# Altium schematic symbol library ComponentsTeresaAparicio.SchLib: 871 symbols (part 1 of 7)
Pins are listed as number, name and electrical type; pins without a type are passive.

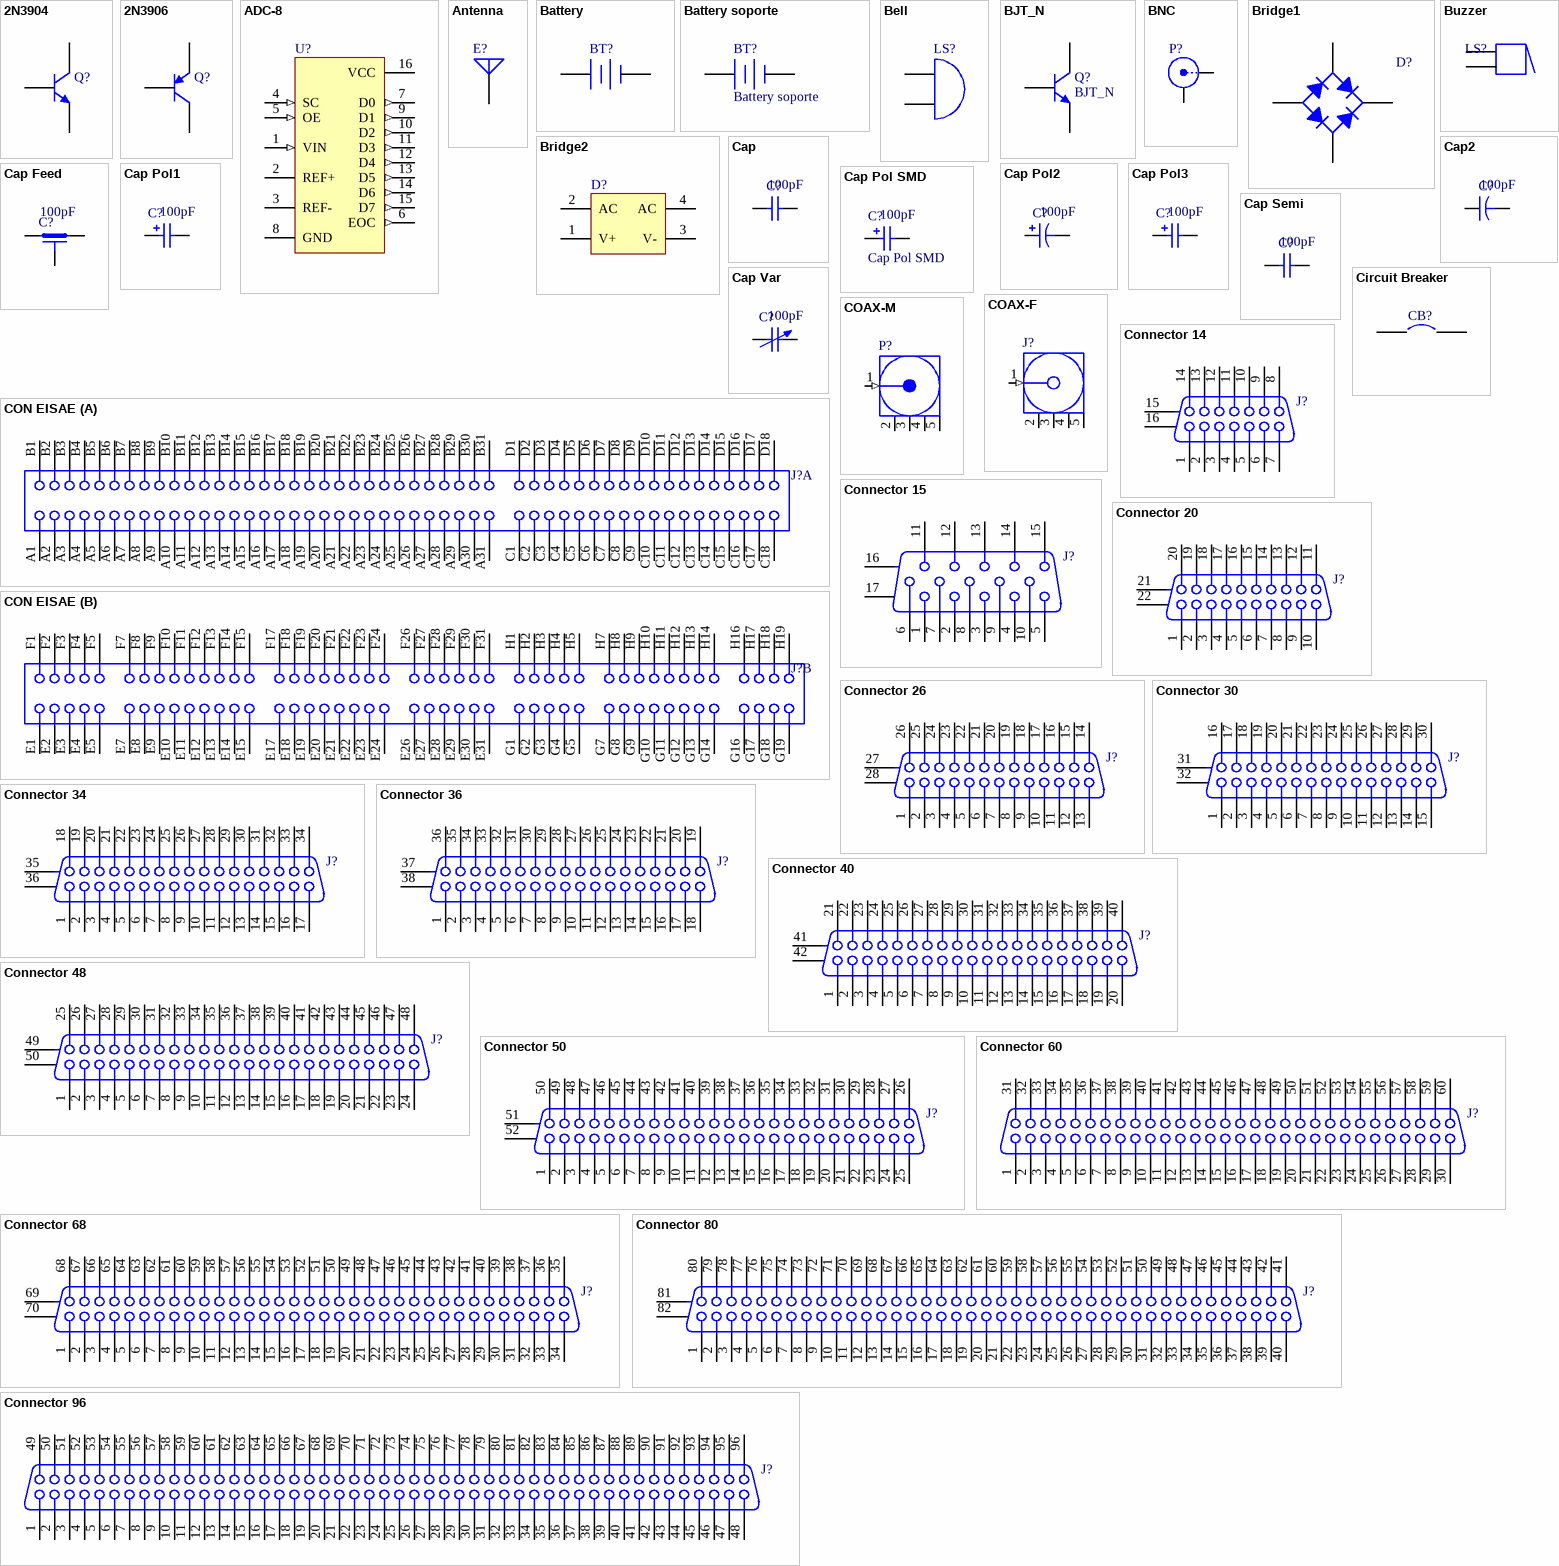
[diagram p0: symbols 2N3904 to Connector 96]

## 2N3904
designator Q?
NPN General Purpose Amplifier
footprint TO-92A (TO, Flat Index; 3 In-Line, Axial Leads; Body Dia. 4.5mm; Leads 0.51 x 0.48 mm (max))
simulation model 2N3904 (NPN)
signal-integrity model 2N3904
pins: 1 E, 2 B, 3 C

## 2N3906
designator Q?
PNP General Purpose Amplifier
footprint TO-92A (TO, Flat Index; 3 In-Line, Axial Leads; Body Dia. 4.5mm; Leads 0.51 x 0.48 mm (max))
simulation model 2N3906 (PNP)
signal-integrity model 2N3906
pins: 1 E, 2 B, 3 C

## ADC-8
designator U?
Generic 8-Bit A/D Converter
footprint SOT403-1_N (TSOP, 16-Leads, Body 5x4.4mm, Pitch 0.65mm, IPC Medium Density)
footprint SOT403-1_L (TSOP, 16-Leads, Body 5x4.4mm, Pitch 0.65mm, IPC High Density)
footprint SOT403-1_M (TSOP, 16-Leads, Body 5x4.4mm, Pitch 0.65mm, IPC Low Density)
simulation model ADC8 (SIMCODE)
pins: 1 VIN (in), 2 REF+, 3 REF-, 4 SC (in), 5 OE (in), 6 EOC (out), 7 D0 (out), 8 GND (power), 9 D1 (out), 10 D2 (out), 11 D3 (out), 12 D4 (out), 13 D5 (out), 14 D6 (out), 15 D7 (out), 16 VCC (power)

## Antenna
designator E?
Generic Antenna
footprint PIN1 (Generic Antenna; 1 Lead)
pins: 1 A

## Battery
designator BT?
Multicell Battery
footprint BAT_Holder (Battery; 2 Leads)
pins: 1 +, 2 -

## Battery soporte
designator BT?
Multicell Battery
footprint BAT-2 (Battery; 2 Leads)
pins: 1 +, 2 -

## Bell
designator LS?
Electrical Bell
footprint PIN2 (Electrical Bell; 2 Leads)
pins: 1 A, 2 B

## BJT_N
designator Q?
NPN General Purpose Amplifier
footprint TO-92A (TO, Flat Index; 3 In-Line, Axial Leads; Body Dia. 4.5mm; Leads 0.51 x 0.48 mm (max))
simulation model 2N3904 (NPN)
signal-integrity model 2N3904
pins: 1 E, 2 B, 3 C

## BNC
designator P?
BNC Elbow Connector
footprint BNC_RA CON (Connector; BNC Elbow)
signal-integrity model Connector
pins: 1 X, 2 Y

## Bridge1
designator D?
Full Wave Diode Bridge
footprint D-38 (Bridge Rectifier; 4 Terminals; Body 9.4 x 9.4 mm (typ); Pitch 5.08 mm)
simulation model BRIDGE (Spice Subcircuit)
pins: 1 K, 2 C, 3 A, 4 C

## Bridge2
designator D?
Diode Bridge
footprint D-46_6A (Bridge Rectifier; 4 Terminals; Body 16.8 x 16.8 mm (typ); Pitch 10.67 mm)
simulation model BRIDGE (Spice Subcircuit)
pins: 1 V+, 2 AC, 3 V-, 4 AC

## Buzzer
designator LS?
Magnetic Transducer Buzzer
footprint Buzzer 5v
pins: 1, 2
1 alternate drawing of the same symbol

## Cap
designator C?  value 100pF
Capacitor
footprint RAD-0.3 (Radial Cap, Thru-Hole; 2 Leads; 0.3 in Pin Spacing)
simulation model CAP (Capacitor)
signal-integrity model Cap
pins: 1, 2

## Cap2
designator C?  value 100pF
Capacitor
footprint CAPR5-4X5 (Capacitor; 2 Leads)
simulation model CAP (Capacitor)
signal-integrity model Cap
pins: 1, 2

## Cap Feed
designator C?  value 100pF
Feed-Through Capacitor; Note: Commonly used for bypassing high-frequency currents to chassis
footprint VR4 (Thru-Hole; 3 Leads)
signal-integrity model Cap Feed
pins: 1, 2, 3

## Cap Pol1
designator C?  value 100pF
Polarized Capacitor (Radial)
footprint RB7.6-15 (Polarized Capacitor (Radial); 2 Leads)
simulation model CAP (Capacitor)
signal-integrity model Cap Pol
pins: 1, 2
1 alternate drawing of the same symbol

## Cap Pol2
designator C?  value 100pF
Polarized Capacitor (Axial)
footprint POLAR0.8 (Polarized Capacitor; 2 Leads)
simulation model CAP (Capacitor)
signal-integrity model Cap Pol
pins: 1, 2
1 alternate drawing of the same symbol

## Cap Pol3
designator C?  value 100pF
Polarized Capacitor (Surface Mount)
footprint C0805 (Chip Capacitor, Body 2.0x1.3mm, IPC High Density)
footprint 1812 (Chip Capacitor, Body 4.5x3.2mm, IPC High Density)
footprint 1825 (Chip Capacitor, Body 4.5x6.4mm, IPC High Density)
footprint C2225 (Chip Capacitor, Body 5.7x6.4mm, IPC High Density)
footprint 2220 (Chip Capacitor, Body 5.7x5.0mm, IPC High Density)
simulation model CAP (Capacitor)
signal-integrity model Cap Pol
pins: 1, 2
1 alternate drawing of the same symbol

## Cap Pol SMD
designator C?  value 100pF
Polarized Capacitor (Radial)
footprint C0805 (Chip Capacitor, Body 2.0x1.3mm, IPC High Density)
simulation model CAP (Capacitor)
signal-integrity model Cap Pol
pins: 1, 2
1 alternate drawing of the same symbol

## Cap Semi
designator C?  value 100pF
Capacitor (Semiconductor SIM Model)
footprint C1206 (Chip Capacitor, Body 3.2x1.6mm, IPC High Density)
footprint 0402 (Chip Capacitor, Body 1.0x0.5mm, IPC High Density)
footprint C2512 (Chip Capacitor, Body 2.54x1.27mm, IPC High Density)
footprint 1608[0603] (Chip Capacitor, Body 1.6x0.8mm, IPC High Density)
footprint C1210 (Chip Capacitor, Body 3.2x2.5mm, IPC High Density)
simulation model CAP (Semiconductor Capacitor)
signal-integrity model C0805
footprint C0805 (Chip Capacitor, Body 2.0x1.3mm, IPC High Density)
pins: 1, 2

## Cap Var
designator C?  value 100pF
Variable or Adjustable Capacitor
footprint C1210_N (Chip Capacitor, Body 3.2x2.5mm, IPC Medium Density)
footprint C1210_L (Chip Capacitor, Body 3.2x2.5mm, IPC High Density)
footprint C1210_M (Chip Capacitor, Body 3.2x2.5mm, IPC Low Density)
signal-integrity model Cap Var
pins: 1, 2

## Circuit Breaker
designator CB?
Circuit Breaker
footprint SPST-2 (Switch; 2 Leads)
pins: 1, 2

## COAX-F
designator J?
RF Coaxial PCB Connector, MCX; Thru-Hole, Right-Angle Mount Socket, Blunt Post Terminal, 50 Ohm Impedance; PCB_Layout: Complies with manufacturer's recommendation.; DrillSize: Corresponds to nominal value.
footprint MCX5.08-H5 (Connector; RF Coaxial, MCX, Thru-Hole; 5 Position; Right-Angle)
pins: 1 Signal (in) "Signal Pin", 2 GND (power), 3 GND (power), 4 GND (power), 5 GND (power)

## COAX-M
designator P?
RF Coaxial PCB Connector, MMCX; Thru-Hole, Vertical Mount Plug,  50 Ohm Impedance; PackageDocument: Rev. A, 16-Jun-1997; PCB_Layout: Complies with manufacturer's recommendation.; DrillSize: Corresponds to nominal value.
footprint MMCX2.54-V5 (Connector; RF Coaxial, MMCX, Thru-Hole; 5 Position; Vertical)
pins: 1 Signal (in) "Signal Pin", 2 GND (power), 3 GND (power), 4 GND (power), 5 GND (power)

## CON EISAE
designator J?
EISA Connector, 188 Positions, Vertical, Pitch 1.27mm; ContactPlating: Gold Flash; PCB_Layout: Complies with manufacturer's recommendation.; DrillSize: Corresponds to nominal value.; Note: Access Keys, E6 E16 E25 F6 F16 F25 G6 G15 H6 H15 not shown.
footprint CARD1.27-2V188 (Connector; EISA, Thru-Hole; 188 Position; Vertical; Pitch 1.27 mm)
signal-integrity model EISA
part A pins: A1 CHCHK#, A2 SD7, A3 SD6, A4 SD5, A5 SD4, A6 SD3, A7 SD2, A8 SD1, A9 SD0, A10 CHRDY, A11 AEN, A12 SA19, A13 SA18, A14 SA17, A15 SA16, A16 SA15, A17 SA14, A18 SA13, A19 SA12, A20 SA11, A21 SA10, A22 SA9, A23 SA8, A24 SA7, A25 SA6, A26 SA5, A27 SA4, A28 SA3, A29 SA2, A30 SA1, A31 SA0, B1 GND "Ground", B2 RESDRV#, B3 +5V "+5 VDC", B4 IRQ2, B5 -5V, B6 DRQ2, B7 -12V, B8 NOWS#, B9 +12V "+12 VDC", B10 GND, B11 SMWTC#, B12 SMRDC#, B13 IOWC#, B14 IORC#, B15 DAK3#, B16 DRQ3, B17 DAK1#, B18 DRQ1, B19 REFRESH#, B20 BCLK, B21 IRQ7, B22 IRQ6, B23 IRQ5, B24 IRQ4, B25 IRQ3, B26 DAK2#, B27 TC, B28 BALE, B29 +5V "+5 VDC", B30 OSC, B31 GND "Ground", C1 SBHE#, C2 LA23, C3 LA22, C4 LA21, C5 LA20, C6 LA19, C7 LA18, C8 LA17, C9 MRDC#, C10 MWTC#, C11 SD8, C12 SD9, C13 SD10, C14 SD11, C15 SD12, C16 SD13, C17 SD14, C18 SD15, D1 M16#, D2 IO16#, D3 IRQ10, D4 IRQ11, D5 IRQ12, D6 IRQ13, D7 IRQ14, D8 DAK0#, D9 DRQ0, D10 DAK5#, D11 DRQ5, D12 DAK6#, D13 DRQ65, D14 DAK7#, D15 DRQ7, D16 +5V "+5 VDC", D17 MASTER16#, D18 GND "Ground"
part B pins: E1 CMD# "Command Phase", E2 START# "Start Phase", E3 EXRDY "EISA Ready", E4 EX32# "EISA Slave Size 32", E5 GND "Ground", E7 EX16# "EISA Slave Size 16", E8 SLBURST# "Slave Burst", E9 MSBURST# "Master Burst", E10 W/R# "Write/Read", E11 GND "Ground", E12 RES "Reserved", E13 RES "Reserved", E14 RES "Reserved", E15 GND "Ground", E17 BE1# "Byte Enable 1", E18 LA31# "Latchable Addressline 31", E19 GND "Ground", E20 LA30# "Latchable Addressline 30", E21 LA28# "Latchable Addressline 28", E22 LA27# "Latchable Addressline 27", E23 LA25# "Latchable Addressline 25", E24 GND "Ground", E26 LA15 "Latchable Addressline 15", E27 LA13 "Latchable Addressline 13", E28 LA12 "Latchable Addressline 12", E29 LA11 "Latchable Addressline 11", E30 GND "Ground", E31 LA9 "Latchable Addressline 9", F1 GND "Ground", F2 +5V "+5 VDC", F3 +5V "+5 VDC", F4 RES "Reserved", F5 RES "Reserved", F7 RES "Reserved", F8 RES "Reserved", F9 +12V "+12 VDC", F10 M/IO# "Memory/Input-Output", F11 LOCK# "Lock bus", F12 RES "Reserved", F13 GND "Ground", F14 RES "Reserved", F15 BE3# "Byte Enable 3", F17 BE2# "Byte Enable 2", F18 BE0# "Byte Enable 0", F19 GND "Ground", F20 +5V "+5 VDC", F21 LA29# "Latchable Addressline 29", F22 GND "Ground", F23 LA26# "Latchable Addressline 26", F24 LA24# "Latchable Addressline 24", F26 LA16 "Latchable Addressline 16", F27 LA14 "Latchable Addressline 14", F28 +5V "+5 VDC", F29 +5V "+5 VDC", F30 GND "Ground", F31 LA10 "Latchable Addressline 10", G1 LA7 "Latchable Addressline 7", G2 GND "Ground", G3 LA4 "Latchable Addressline 4", G4 LA3 "Latchable Addressline 3", G5 GND "Ground", G7 D17 "Data 17", G8 D19 "Data 19", G9 D20 "Data 20", G10 D22 "Data 22", G11 GND "Ground", G12 D25 "Data 25", G13 D26 "Data 26", G14 D28 "Data 28", G16 GND "Ground", G17 D30 "Data 30", G18 D31 "Data 31", G19 MREQx "Master Request", H1 LA8 "Latchable Addressline 8", H2 LA6 "Latchable Addressline 6", H3 LA5 "Latchable Addressline 5", H4 +5V "+5 VDC", H5 LA2 "Latchable Addressline 2", H7 D16 "Data 16", H8 D18 "Data 18", H9 GND "Ground", H10 D21 "Data 21", H11 D23 "Data 23", H12 D24 "Data 24", H13 GND "Ground", H14 D27 "Data 27", H16 D29 "Data 29", H17 +5V "+5 VDC", H18 +5V "+5 VDC", H19 MAKx "Master Acknowledge"

## Connector 14
designator J?
Receptacle Header Assemby; PackageDocument: B; Positions: 14
footprint CHAMP1.27-2H14A (Connector; 14 Position; Right Angle; Pitch 1.27 mm)
signal-integrity model Connector
pins: 1, 2, 3, 4, 5, 6, 7, 8, 9, 10, 11, 12, 13, 14, 15 MH1, 16 MH2

## Connector 15
designator J?
Receptacle Assembly, 15-Pin, Sim Line Connector; PackageDocument: B; Positions: 15; Gender: Receptacle Header
footprint 050DSUB0.762-4H15 (Connector; D Subminiature; 15 Position; Right Angle; Pitch 0.762 mm)
signal-integrity model Connector
pins: 1, 2, 3, 4, 5, 6, 7, 8, 9, 10, 11, 12, 13, 14, 15, 16 MH1, 17 MH2

## Connector 20
designator J?
Receptacle Header Assemby; PackageDocument: B; Positions: 20
footprint CHAMP1.27-2H20 (Connector; 20 Position; Right Angle; Pitch 1.27 mm)
signal-integrity model Connector
pins: 1, 2, 3, 4, 5, 6, 7, 8, 9, 10, 11, 12, 13, 14, 15, 16, 17, 18, 19, 20, 21 MH1, 22 MH2

## Connector 26
designator J?
Receptacle Header Assemby; PackageDocument: B; Positions: 26
footprint CHAMP1.27-2H26 (Connector; 26 Position; Right Angle; Pitch 1.27 mm)
signal-integrity model Connector
pins: 1, 2, 3, 4, 5, 6, 7, 8, 9, 10, 11, 12, 13, 14, 15, 16, 17, 18, 19, 20, 21, 22, 23, 24, 25, 26, 27 MH1, 28 MH2

## Connector 30
designator J?
Plug Assembly, 30-Pin Connector; PackageDocument: E; Positions: 30; Gender: Receptacle Header
footprint 050DSUB1.27-2H30 (Connector; D Subminiature; 30 Position; Right Angle; Pitch 1.27 mm)
signal-integrity model Connector
pins: 1, 2, 3, 4, 5, 6, 7, 8, 9, 10, 11, 12, 13, 14, 15, 16, 17, 18, 19, 20, 21, 22, 23, 24, 25, 26, 27, 28, 29, 30, 31 MH1, 32 MH2

## Connector 34
designator J?
Plug Assembly, 34-Pin Connector; PackageDocument: F; Positions: 34; Gender: Receptacle Header
footprint 050DSUB1.27-2H34 (Connector; D Subminiature; 34 Position; Right Angle; Pitch 1.27 mm)
signal-integrity model Connector
pins: 1, 2, 3, 4, 5, 6, 7, 8, 9, 10, 11, 12, 13, 14, 15, 16, 17, 18, 19, 20, 21, 22, 23, 24, 25, 26, 27, 28, 29, 30, 31, 32, 33, 34, 35 MH1, 36 MH2

## Connector 36
designator J?
Receptacle Header Assemby; PackageDocument: B; Positions: 36
footprint CHAMP1.27-2H36 (Connector; 36 Position; Right Angle; Pitch 1.27 mm)
signal-integrity model Connector
pins: 1, 2, 3, 4, 5, 6, 7, 8, 9, 10, 11, 12, 13, 14, 15, 16, 17, 18, 19, 20, 21, 22, 23, 24, 25, 26, 27, 28, 29, 30, 31, 32, 33, 34, 35, 36, 37 MH1, 38 MH2

## Connector 40
designator J?
Plug Assembly, 40-Pin Connector; PackageDocument: E; Positions: 40; Gender: Receptacle Header
footprint 050DSUB1.27-2H40 (Connector; D Subminiature; 40 Position; Right Angle; Pitch 1.27 mm)
signal-integrity model Connector
pins: 1, 2, 3, 4, 5, 6, 7, 8, 9, 10, 11, 12, 13, 14, 15, 16, 17, 18, 19, 20, 21, 22, 23, 24, 25, 26, 27, 28, 29, 30, 31, 32, 33, 34, 35, 36, 37, 38, 39, 40, 41 MH1, 42 MH2

## Connector 48
designator J?
Plug Assembly, 48-Pin Connector; PackageDocument: F; Positions: 48; Gender: Receptacle Header
footprint 050DSUB1.27-2H48 (Connector; D Subminiature; 48 Position; Right Angle; Pitch 1.27 mm)
signal-integrity model Connector
pins: 1, 2, 3, 4, 5, 6, 7, 8, 9, 10, 11, 12, 13, 14, 15, 16, 17, 18, 19, 20, 21, 22, 23, 24, 25, 26, 27, 28, 29, 30, 31, 32, 33, 34, 35, 36, 37, 38, 39, 40, 41, 42, 43, 44, 45, 46, 47, 48, 49 MH1, 50 MH2

## Connector 50
designator J?
Receptacle Header Assemby; PackageDocument: B; Positions: 50
footprint CHAMP1.27-2H50 (Connector; 50 Position; Right Angle; Pitch 1.27 mm)
signal-integrity model Connector
pins: 1, 2, 3, 4, 5, 6, 7, 8, 9, 10, 11, 12, 13, 14, 15, 16, 17, 18, 19, 20, 21, 22, 23, 24, 25, 26, 27, 28, 29, 30, 31, 32, 33, 34, 35, 36, 37, 38, 39, 40, 41, 42, 43, 44, 45, 46, 47, 48, 49, 50, 51 MH1, 52 MH2

## Connector 60
designator J?
Plug Assembly, 60-Pin Connector; PackageDocument: D; Positions: 60; Gender: Receptacle Header
footprint 050DSUB1.27-V60 (Connector; D Subminiature; 60 Position; Vertical; Pitch 1.27 mm)
signal-integrity model Connector
pins: 1, 2, 3, 4, 5, 6, 7, 8, 9, 10, 11, 12, 13, 14, 15, 16, 17, 18, 19, 20, 21, 22, 23, 24, 25, 26, 27, 28, 29, 30, 31, 32, 33, 34, 35, 36, 37, 38, 39, 40, 41, 42, 43, 44, 45, 46, 47, 48, 49, 50, 51, 52, 53, 54, 55, 56, 57, 58, 59, 60

## Connector 68
designator J?
Receptacle Header Assemby; PackageDocument: B; Positions: 68
footprint CHAMP1.27-2H68 (Connector; 68 Position; Right Angle; Pitch 1.27 mm)
signal-integrity model Connector
pins: 1, 2, 3, 4, 5, 6, 7, 8, 9, 10, 11, 12, 13, 14, 15, 16, 17, 18, 19, 20, 21, 22, 23, 24, 25, 26, 27, 28, 29, 30, 31, 32, 33, 34, 35, 36, 37, 38, 39, 40, 41, 42, 43, 44, 45, 46, 47, 48, 49, 50, 51, 52, 53, 54, 55, 56, 57, 58, 59, 60, 61, 62, 63, 64, 65, 66, 67, 68, 69 MH1, 70 MH2

## Connector 80
designator J?
Receptacle Header Assemby; PackageDocument: C; Positions: 80
footprint CHAMP1.27-2V80 (Connector; 80 Position; Vertical; Pitch 1.27 mm)
signal-integrity model Connector
pins: 1, 2, 3, 4, 5, 6, 7, 8, 9, 10, 11, 12, 13, 14, 15, 16, 17, 18, 19, 20, 21, 22, 23, 24, 25, 26, 27, 28, 29, 30, 31, 32, 33, 34, 35, 36, 37, 38, 39, 40, 41, 42, 43, 44, 45, 46, 47, 48, 49, 50, 51, 52, 53, 54, 55, 56, 57, 58, 59, 60, 61, 62, 63, 64, 65, 66, 67, 68, 69, 70, 71, 72, 73, 74, 75, 76, 77, 78, 79, 80, 81 MH1, 82 MH2

## Connector 96
designator J?
Plug Assembly, 96-Pin Connector; PackageDocument: C; Positions: 96; Gender: Receptacle Header
footprint 050DSUB1.27-H96 (Connector; D Subminiature; 96 Position; Right Angle; Pitch 1.27 mm)
signal-integrity model Connector
pins: 1, 2, 3, 4, 5, 6, 7, 8, 9, 10, 11, 12, 13, 14, 15, 16, 17, 18, 19, 20, 21, 22, 23, 24, 25, 26, 27, 28, 29, 30, 31, 32, 33, 34, 35, 36, 37, 38, 39, 40, 41, 42, 43, 44, 45, 46, 47, 48, 49, 50, 51, 52, 53, 54, 55, 56, 57, 58, 59, 60, 61, 62, 63, 64, 65, 66, 67, 68, 69, 70, 71, 72, 73, 74, 75, 76, 77, 78, 79, 80, 81, 82, 83, 84, 85, 86, 87, 88, 89, 90, 91, 92, 93, 94, 95, 96

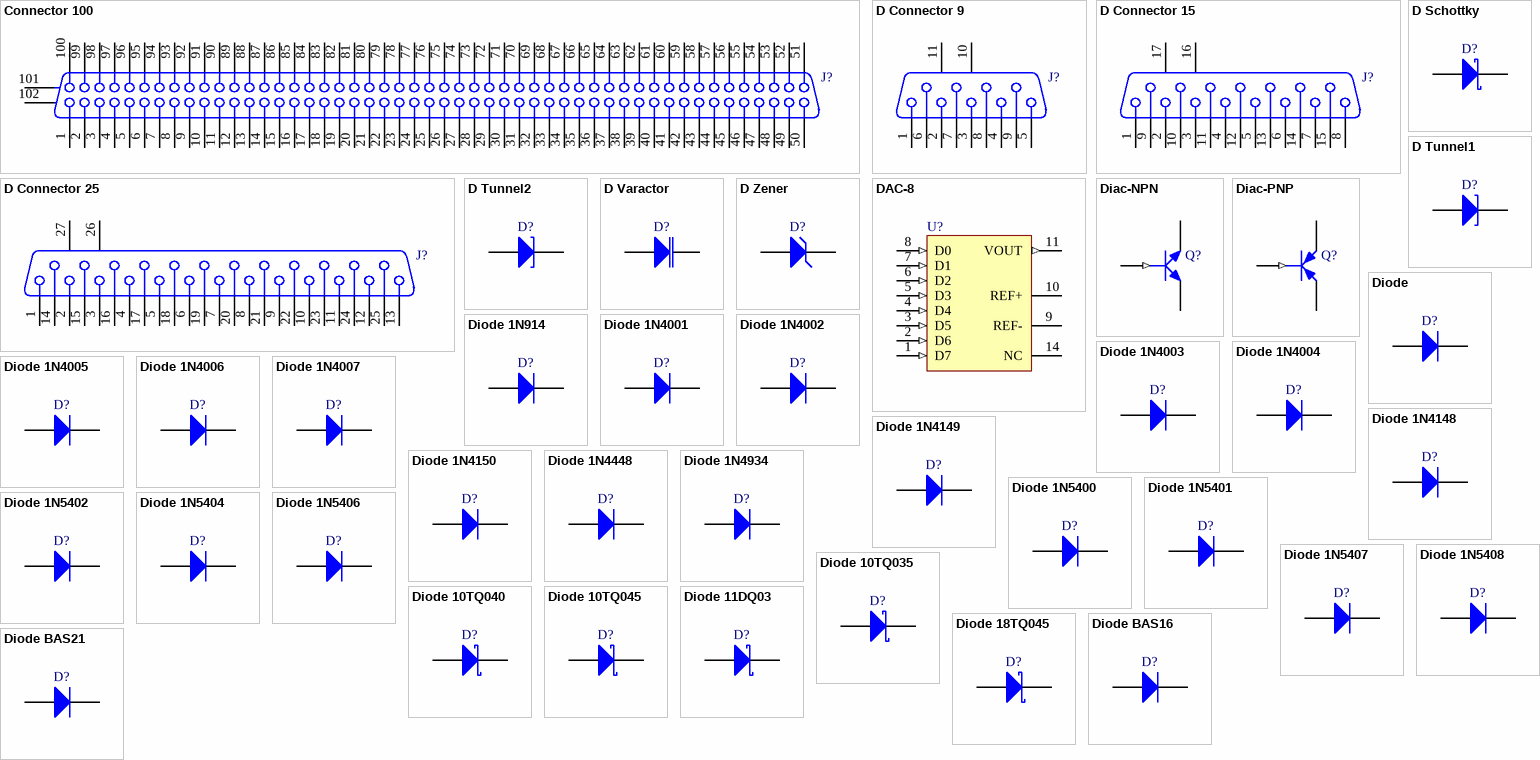
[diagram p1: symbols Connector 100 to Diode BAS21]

## Connector 100
designator J?
Receptacle Header Assemby; PackageDocument: B; Positions: 100
footprint CHAMP1.27-2H100 (Connector; 100 Position; Right Angle; Pitch 1.27 mm)
signal-integrity model Connector
pins: 1, 2, 3, 4, 5, 6, 7, 8, 9, 10, 11, 12, 13, 14, 15, 16, 17, 18, 19, 20, 21, 22, 23, 24, 25, 26, 27, 28, 29, 30, 31, 32, 33, 34, 35, 36, 37, 38, 39, 40, 41, 42, 43, 44, 45, 46, 47, 48, 49, 50, 51, 52, 53, 54, 55, 56, 57, 58, 59, 60, 61, 62, 63, 64, 65, 66, 67, 68, 69, 70, 71, 72, 73, 74, 75, 76, 77, 78, 79, 80, 81, 82, 83, 84, 85, 86, 87, 88, 89, 90, 91, 92, 93, 94, 95, 96, 97, 98, 99, 100, 101 MH1, 102 MH2

## D Connector 9
designator J?
Receptacle Assembly, 9 Position, Right Angle; PackageDocument: O; Positions: 9
footprint DSUB1.385-2H9 (Connector; D Subminiature; 9 Position; Right Angle; Pitch 1.385 mm)
signal-integrity model Connector
pins: 1, 2, 3, 4, 5, 6, 7, 8, 9, 10 MH1, 11 MH2

## D Connector 15
designator J?
Receptacle Assembly, 15 Position, Right Angle; PackageDocument: O; Positions: 15
footprint DSUB1.385-2H15 (Connector; D Subminiature; 15 Position; Right Angle; Pitch 1.385 mm)
signal-integrity model Connector
pins: 1, 2, 3, 4, 5, 6, 7, 8, 9, 10, 11, 12, 13, 14, 15, 16 MH1, 17 MH2

## D Connector 25
designator J?
Receptacle Assembly, 25 Position, Right Angle; PackageDocument: U; Positions: 25
footprint DSUB1.385-2H25A (Connector; D Subminiature; 25 Position; Right Angle; Pitch 1.385 mm)
signal-integrity model Connector
pins: 1, 2, 3, 4, 5, 6, 7, 8, 9, 10, 11, 12, 13, 14, 15, 16, 17, 18, 19, 20, 21, 22, 23, 24, 25, 26 MH1, 27 MH2

## D Schottky
designator D?
Schottky Diode
footprint SMB (DO-214-AA/SMB; 2 C-Bend Leads; Body 5.3 x 3.6 mm, inc. leads (LxW))
simulation model SKYDIODE (Diode)
signal-integrity model D Schottky
pins: 1 A, 2 K

## D Tunnel1
designator D?
Tunnel Diode - RLC Model
footprint 3.2X1.6X1.1 (SMT LED; 2 Flat Leads)
simulation model DTUNNEL1 (Spice Subcircuit)
signal-integrity model D Tunnel
pins: 1 A, 2 K

## D Tunnel2
designator D?
Tunnel Diode - Dependent Source Model
footprint DIODE-0.4 (Diode, Thru-Hole; 2 Leads; 0.4 in Pin Spacing)
simulation model DTUNNEL2 (Spice Subcircuit)
signal-integrity model D Tunnel
pins: 1 A, 2 K

## D Varactor
designator D?
Variable Capacitance Diode; Note: Pin 2 is not connected and not drawn.
footprint SOT23_N (SOT23, 3-Leads, Body 2.9x1.3mm, Pitch 0.95mm, Lead Span 2.3mm - Reverse Pinning, IPC Medium Density)
footprint SOT23_L (SOT23, 3-Leads, Body 2.9x1.3mm, Pitch 0.95mm, Lead Span 2.3mm - Reverse Pinning, IPC High Density)
footprint SOT23_M (SOT23, 3-Leads, Body 2.9x1.3mm, Pitch 0.95mm, Lead Span 2.3mm - Reverse Pinning, IPC Low Density)
simulation model BBY31 (Diode)
signal-integrity model D Varactor
pins: 1 K, 3 A

## D Zener
designator D?
Zener Diode
footprint DIODE-0.7 (Diode, Thru-Hole; 2 Leads; 0.7 in Pin Spacing)
simulation model ZENER (Diode)
signal-integrity model D Zener
pins: 1 A, 2 K

## DAC-8
designator U?
Generic 8-Bit D/A Converter
footprint SOT402-1_N (TSOP, 14-Leads, Body 5x4.4mm, Pitch 0.65mm, IPC Medium Density)
footprint SOT402-1_L (TSOP, 14-Leads, Body 5x4.4mm, Pitch 0.65mm, IPC High Density)
footprint SOT402-1_M (TSOP, 14-Leads, Body 5x4.4mm, Pitch 0.65mm, IPC Low Density)
simulation model DAC8 (SIMCODE)
pins: 1 D7 (in), 2 D6 (in), 3 D5 (in), 4 D4 (in), 5 D3 (in), 6 D2 (in), 7 D1 (in), 8 D0 (in), 9 REF-, 10 REF+, 11 VOUT (out), 12 GND (power) hidden to GND, 13 VCC (power) hidden to VCC, 14 NC

## Diac-NPN
designator Q?
DIAC
footprint TO-262-AA (TO, Thru-Hole, Vertical, Heatsink Mounted; 3 In-Line Leads; Pitch 2.54 mm)
pins: 1 B (in), 2 C, 3 E

## Diac-PNP
designator Q?
DIAC
footprint SOT89M (SOT89, 3-Leads, Body 4.5x2.4 mm, Pitch 1.5mm, Lead Span 4.1mm, IPC Low Density)
footprint SOT89N (SOT89, 3-Leads, Body 4.5x2.4 mm, Pitch 1.5mm, Lead Span 4.1mm, IPC Medium Density)
footprint SOT89L (SOT89, 3-Leads, Body 4.5x2.4 mm, Pitch 1.5mm, Lead Span 4.1mm, IPC High Density)
pins: 1 B (in), 2 E, 3 C

## Diode
designator D?
Default Diode
footprint SMC (DO-214-AB/SMC; 2 C-Bend Leads; Body 7.9 x 5.9 mm, inc. leads (LxW))
simulation model DIODE (Diode)
signal-integrity model Diode
pins: 1 A, 2 K

## Diode 1N914
designator D?
High Conductance Fast Diode
footprint DO-35 (Diode, Axial; Body 3.8 x 1.9 mm (LxDia. max), Lead Dia. 0.53 mm (max))
simulation model 1N914 (DIODE)
signal-integrity model 1N914
pins: 1 A, 2 K

## Diode 1N4001
designator D?
1 Amp General Purpose Rectifier
footprint DO-41 (Diode, Axial; Body 5.2 x 2.7 mm (LxDia. max), Lead Dia. 0.86 mm (max))
simulation model 1N4001 (DIODE)
signal-integrity model 1N4001
pins: 1 A, 2 K

## Diode 1N4002
designator D?
1 Amp General Purpose Rectifier
footprint DO-41 (Diode, Axial; Body 5.2 x 2.7 mm (LxDia. max), Lead Dia. 0.86 mm (max))
simulation model 1N4002 (DIODE)
signal-integrity model 1N4002
pins: 1 A, 2 K

## Diode 1N4003
designator D?
1 Amp General Purpose Rectifier
footprint DO-41 (Diode, Axial; Body 5.2 x 2.7 mm (LxDia. max), Lead Dia. 0.86 mm (max))
simulation model 1N4003 (DIODE)
signal-integrity model 1N4003
pins: 1 A, 2 K

## Diode 1N4004
designator D?
1 Amp General Purpose Rectifier
footprint DO-41 (Diode, Axial; Body 5.2 x 2.7 mm (LxDia. max), Lead Dia. 0.86 mm (max))
simulation model 1N4004 (DIODE)
signal-integrity model 1N4004
pins: 1 A, 2 K

## Diode 1N4005
designator D?
1 Amp General Purpose Rectifier
footprint DO-41 (Diode, Axial; Body 5.2 x 2.7 mm (LxDia. max), Lead Dia. 0.86 mm (max))
simulation model 1N4005 (DIODE)
signal-integrity model 1N4005
pins: 1 A, 2 K

## Diode 1N4006
designator D?
1 Amp General Purpose Rectifier
footprint DO-41 (Diode, Axial; Body 5.2 x 2.7 mm (LxDia. max), Lead Dia. 0.86 mm (max))
simulation model 1N4006 (DIODE)
signal-integrity model 1N4006
pins: 1 A, 2 K

## Diode 1N4007
designator D?
1 Amp General Purpose Rectifier
footprint DO-41 (Diode, Axial; Body 5.2 x 2.7 mm (LxDia. max), Lead Dia. 0.86 mm (max))
simulation model 1N4007 (DIODE)
signal-integrity model 1N4007
pins: 1 A, 2 K

## Diode 1N4148
designator D?
High Conductance Fast Diode
footprint DO-35 (Diode, Axial; Body 3.8 x 1.9 mm (LxDia. max), Lead Dia. 0.53 mm (max))
simulation model 1N4148 (DIODE)
signal-integrity model 1N4148
pins: 1 A, 2 K

## Diode 1N4149
designator D?
Computer Diode
footprint DO-35A (Diode, Axial; Body 4.6 x 1.9 mm (LxDia. max), Lead Dia. 0.53 mm (max))
simulation model 1N4149 (DIODE)
pins: 1 A, 2 K

## Diode 1N4150
designator D?
High Conductance Ultra Fast Diode
footprint DO-35 (Diode, Axial; Body 3.8 x 1.9 mm (LxDia. max), Lead Dia. 0.53 mm (max))
simulation model 1N4150 (DIODE)
signal-integrity model 1N4150
pins: 1 A, 2 K

## Diode 1N4448
designator D?
High Conductance Fast Diode
footprint DO-35 (Diode, Axial; Body 3.8 x 1.9 mm (LxDia. max), Lead Dia. 0.53 mm (max))
simulation model 1N4448 (DIODE)
signal-integrity model 1N4448
pins: 1 A, 2 K

## Diode 1N4934
designator D?
1 Amp Fast Recovery Rectifier
footprint DO-41 (Diode, Axial; Body 5.2 x 2.7 mm (LxDia. max), Lead Dia. 0.86 mm (max))
simulation model 1N4934 (DIODE)
signal-integrity model 1N4934
pins: 1 A, 2 K

## Diode 1N5400
designator D?
3 Amp General Purpose Rectifier
footprint DO-201AD (Diode, Axial; Body 9.5 x 5.6 mm (LxDia. max), Lead Dia. 1.32 mm (max))
simulation model 1N5400 (DIODE)
signal-integrity model 1N5400
pins: 1 A, 2 K

## Diode 1N5401
designator D?
3 Amp General Purpose Rectifier
footprint DO-201AD (Diode, Axial; Body 9.5 x 5.6 mm (LxDia. max), Lead Dia. 1.32 mm (max))
simulation model 1N5401 (DIODE)
signal-integrity model 1N5401
pins: 1 A, 2 K

## Diode 1N5402
designator D?
3 Amp General Purpose Rectifier
footprint DO-201AD (Diode, Axial; Body 9.5 x 5.6 mm (LxDia. max), Lead Dia. 1.32 mm (max))
simulation model 1N5402 (DIODE)
signal-integrity model 1N5402
pins: 1 A, 2 K

## Diode 1N5404
designator D?
3 Amp General Purpose Rectifier
footprint DO-201AD (Diode, Axial; Body 9.5 x 5.6 mm (LxDia. max), Lead Dia. 1.32 mm (max))
simulation model 1N5404 (DIODE)
signal-integrity model 1N5404
pins: 1 A, 2 K

## Diode 1N5406
designator D?
3 Amp General Purpose Rectifier
footprint DO-201AD (Diode, Axial; Body 9.5 x 5.6 mm (LxDia. max), Lead Dia. 1.32 mm (max))
simulation model 1N5406 (DIODE)
signal-integrity model 1N5406
pins: 1 A, 2 K

## Diode 1N5407
designator D?
3 Amp Medium Power Silicon Rectifier Diode
footprint DO-201AD (Diode, Axial; Body 9.5 x 5.3 mm (LxDia. max), Lead Dia. 1.32 mm (max))
simulation model 1N5407 (DIODE)
signal-integrity model 1N5407
pins: 1 A, 2 K

## Diode 1N5408
designator D?
3 Amp Medium Power Silicon Rectifier Diode
footprint DO-201AD (Diode, Axial; Body 9.5 x 5.3 mm (LxDia. max), Lead Dia. 1.32 mm (max))
simulation model 1N5408 (DIODE)
signal-integrity model 1N5408
pins: 1 A, 2 K

## Diode 10TQ035
designator D?
Schottky Rectifier; Note: Terminal 2 is the TAB and is electrically connected to the cathode
footprint TO-220AC (TO, Thru-Hole, Vertical, Heatsink Mounted; 3 In-Line Leads (1 Absent); Pitch 2.54 mm)
simulation model 10TQ035 (DIODE)
pins: 1 K, 3 A

## Diode 10TQ040
designator D?
Schottky Rectifier; Note: Terminal 2 is the TAB and is electrically connected to the cathode
footprint TO-220AC (TO, Thru-Hole, Vertical, Heatsink Mounted; 3 In-Line Leads (1 Absent); Pitch 2.54 mm)
simulation model 10TQ040 (DIODE)
pins: 1 K, 3 A

## Diode 10TQ045
designator D?
Schottky Rectifier; Note: Terminal 2 is the TAB and is electrically connected to the cathode
footprint TO-220AC (TO, Thru-Hole, Vertical, Heatsink Mounted; 3 In-Line Leads (1 Absent); Pitch 2.54 mm)
simulation model 10TQ045 (DIODE)
pins: 1 K, 3 A

## Diode 11DQ03
designator D?
Schottky Rectifier
footprint DO-204AL (Diode, Axial; Body 5.2 x 2.7 mm (LxDia. max), Lead Dia. 0.86 mm (max))
simulation model 11DQ03 (DIODE)
pins: 1 A, 2 K

## Diode 18TQ045
designator D?
Schottky Rectifier; Note: Terminal 2 is the TAB and is electrically connected to the cathode
footprint TO-220AC (TO, Thru-Hole, Vertical, Heatsink Mounted; 3 In-Line Leads (1 Absent); Pitch 2.54 mm)
simulation model 18TQ045 (DIODE)
pins: 1 K, 3 A

## Diode BAS16
designator D?
Silicon Switching Diode for High-Speed Switching; Note: Pin 2 is not connected and not drawn.
footprint SOT-23_N (SOT23, 3-Leads, Body 2.9x1.3mm, Pitch 0.95mm, Lead Span 2.5mm, IPC Medium Density)
footprint SOT-23_L (SOT23, 3-Leads, Body 2.9x1.3mm, Pitch 0.95mm, Lead Span 2.5mm, IPC High Density)
footprint SOT-23_M (SOT23, 3-Leads, Body 2.9x1.3mm, Pitch 0.95mm, Lead Span 2.5mm, IPC Low Density)
simulation model BAS16 (SUBCKT)
pins: 1 A, 3 K

## Diode BAS21
designator D?
Silicon Switching Diode for High-Speed, High-Voltage Switching; Note: Pin 2 is not connected and not drawn.
footprint SOT-23_N (SOT23, 3-Leads, Body 2.9x1.3mm, Pitch 0.95mm, Lead Span 2.5mm, IPC Medium Density)
footprint SOT-23_L (SOT23, 3-Leads, Body 2.9x1.3mm, Pitch 0.95mm, Lead Span 2.5mm, IPC High Density)
footprint SOT-23_M (SOT23, 3-Leads, Body 2.9x1.3mm, Pitch 0.95mm, Lead Span 2.5mm, IPC Low Density)
simulation model BAS21 (DIODE)
pins: 1 A, 3 K

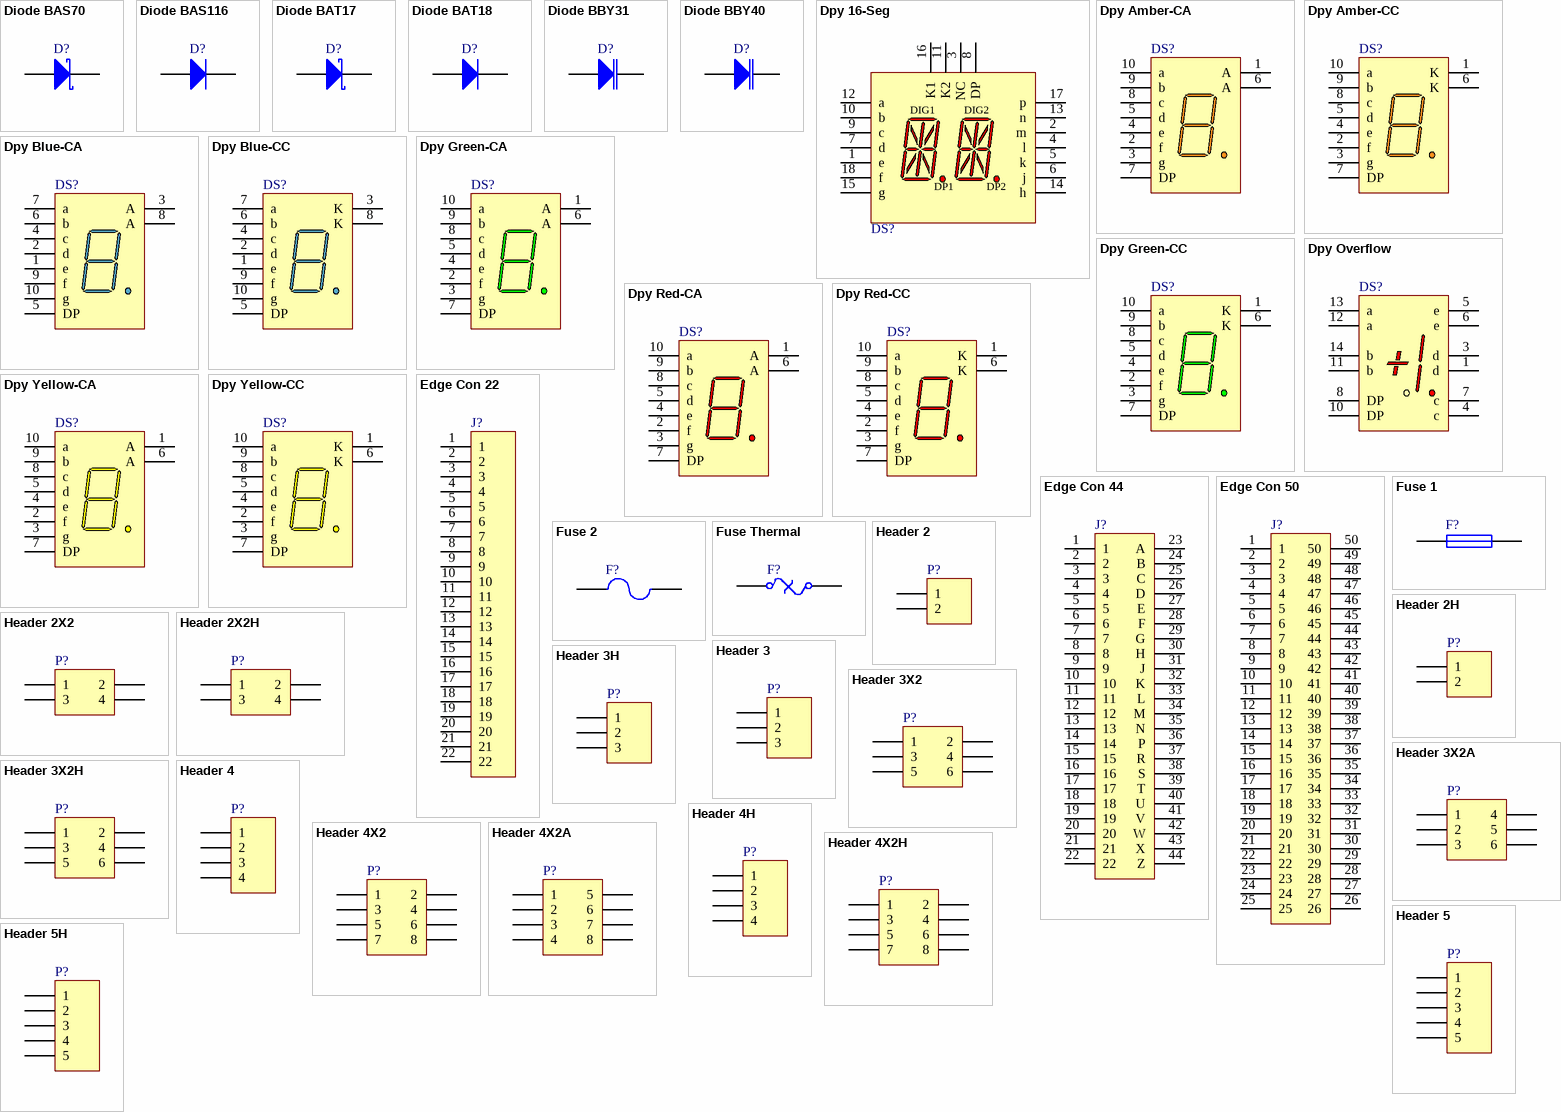
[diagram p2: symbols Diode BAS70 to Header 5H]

## Diode BAS70
designator D?
Silicon AF Schottky Diode for High-Speed Switching; Note: Pin 2 is not connected and not drawn.
footprint SOT-23_N (SOT23, 3-Leads, Body 2.9x1.3mm, Pitch 0.95mm, Lead Span 2.5mm, IPC Medium Density)
footprint SOT-23_L (SOT23, 3-Leads, Body 2.9x1.3mm, Pitch 0.95mm, Lead Span 2.5mm, IPC High Density)
footprint SOT-23_M (SOT23, 3-Leads, Body 2.9x1.3mm, Pitch 0.95mm, Lead Span 2.5mm, IPC Low Density)
simulation model BAS70 (DIODE)
pins: 1 A, 3 K

## Diode BAS116
designator D?
Silicon Low Leakage Diode; Note: Pin 2 is not connected and not drawn.
footprint SOT-23_N (SOT23, 3-Leads, Body 2.9x1.3mm, Pitch 0.95mm, Lead Span 2.5mm, IPC Medium Density)
footprint SOT-23_L (SOT23, 3-Leads, Body 2.9x1.3mm, Pitch 0.95mm, Lead Span 2.5mm, IPC High Density)
footprint SOT-23_M (SOT23, 3-Leads, Body 2.9x1.3mm, Pitch 0.95mm, Lead Span 2.5mm, IPC Low Density)
simulation model BAS116 (DIODE)
pins: 1 A, 3 K

## Diode BAT17
designator D?
Silicon RF Schottky Diode for Mixer Applications in the VHF/UHF Range; Note: Pin 2 is not connected and not drawn.
footprint SOT-23_N (SOT23, 3-Leads, Body 2.9x1.3mm, Pitch 0.95mm, Lead Span 2.5mm, IPC Medium Density)
footprint SOT-23_L (SOT23, 3-Leads, Body 2.9x1.3mm, Pitch 0.95mm, Lead Span 2.5mm, IPC High Density)
footprint SOT-23_M (SOT23, 3-Leads, Body 2.9x1.3mm, Pitch 0.95mm, Lead Span 2.5mm, IPC Low Density)
simulation model D188 (DIODE)
pins: 1 A, 3 K

## Diode BAT18
designator D?
Low-Loss RF Switching Diode; Note: Pin 2 is not connected and not drawn.
footprint SOT-23_N (SOT23, 3-Leads, Body 2.9x1.3mm, Pitch 0.95mm, Lead Span 2.5mm, IPC Medium Density)
footprint SOT-23_L (SOT23, 3-Leads, Body 2.9x1.3mm, Pitch 0.95mm, Lead Span 2.5mm, IPC High Density)
footprint SOT-23_M (SOT23, 3-Leads, Body 2.9x1.3mm, Pitch 0.95mm, Lead Span 2.5mm, IPC Low Density)
simulation model BAT18 (DIODE)
pins: 1 A, 3 K

## Diode BBY31
designator D?
SOT23 Silicon Planar Variable Capacitance Diode; Note: Pin 2 is not connected and not drawn.
footprint SOT23_N (SOT23, 3-Leads, Body 2.9x1.3mm, Pitch 0.95mm, Lead Span 2.3mm - Reverse Pinning, IPC Medium Density)
footprint SOT23_L (SOT23, 3-Leads, Body 2.9x1.3mm, Pitch 0.95mm, Lead Span 2.3mm - Reverse Pinning, IPC High Density)
footprint SOT23_M (SOT23, 3-Leads, Body 2.9x1.3mm, Pitch 0.95mm, Lead Span 2.3mm - Reverse Pinning, IPC Low Density)
simulation model BBY31 (DIODE)
pins: 1 K, 3 A

## Diode BBY40
designator D?
SOT23 Silicon Planar Variable Capacitance Diode; Note: Pin 2 is not connected and not drawn.
footprint SOT23_N (SOT23, 3-Leads, Body 2.9x1.3mm, Pitch 0.95mm, Lead Span 2.3mm - Reverse Pinning, IPC Medium Density)
footprint SOT23_L (SOT23, 3-Leads, Body 2.9x1.3mm, Pitch 0.95mm, Lead Span 2.3mm - Reverse Pinning, IPC High Density)
footprint SOT23_M (SOT23, 3-Leads, Body 2.9x1.3mm, Pitch 0.95mm, Lead Span 2.3mm - Reverse Pinning, IPC Low Density)
simulation model BBY40 (DIODE)
pins: 1 K, 3 A

## Dpy 16-Seg
designator DS?
13.7 mm Gray Surface As AlInGaP Red Alphanumeric Display: 2-Character, CC
footprint HDSP-A2 (LED, Alphanumeric Display, 13.8 mm, Dual Character; 18 Leads; Row Space 15.24 mm; Pitch 2.54 mm)
simulation model HDSP_A27C (SUBCKT)
pins: 1 e "Digits (1&2) e Anode", 2 m "Digits (1&2) m Anode", 3 NC "No Connect", 4 l "Digits (1&2) l Anode", 5 k "Digits (1&2) k Anode", 6 j "Digits (1&2) j Anode", 7 d "Digits (1&2) d Anode", 8 DP "Digit 1&2 DP Anode", 9 c "Digits (1&2) c Anode", 10 b "Digits (1&2) b Anode", 11 K2 "Digit 2 Common Cathode", 12 a "Digits (1&2) a Anode", 13 n "Digits (1&2) n Anode", 14 h "Digits (1&2) h Anode", 15 g "Digits (1&2) g Anode", 16 K1 "Digit 1 Common Cathode", 17 p "Digits (1&2) p Anode", 18 f "Digits (1&2) f Anode"

## Dpy Amber-CA
designator DS?
7.62 mm Black Surface Orange 7-Segment Display: CA, RH DP; MinimumIntensity: 354 ucd; Note: IF = 5 mA; Note: Pins 1 and 6 are redundant Anodes.
footprint A (LED, 7-Segment Display, 7.62 mm, RHD; 10 Leads; Row Space 5.08 mm; Pitch 2.54 mm)
simulation model HDSP_A211 (SUBCKT)
pins: 1 A "Anode", 2 f "Cathode", 3 g "Cathode", 4 e "Cathode", 5 d "Cathode", 6 A "Anode", 7 DP "Cathode", 8 c "Cathode", 9 b "Cathode", 10 a "Cathode"

## Dpy Amber-CC
designator DS?
7.62 mm Black Surface Orange 7-Segment Display: CC, RH DP; MinimumIntensity: 354 ucd; Note: IF = 5 mA; Note: Pins 1 and 6 are redundant Cathodes.
footprint A (LED, 7-Segment Display, 7.62 mm, RHD; 10 Leads; Row Space 5.08 mm; Pitch 2.54 mm)
simulation model HDSP_A213 (SUBCKT)
pins: 1 K "Cathode", 2 f "Anode", 3 g "Anode", 4 e "Anode", 5 d "Anode", 6 K "Cathode", 7 DP "Anode", 8 c "Anode", 9 b "Anode", 10 a "Anode"

## Dpy Blue-CA
designator DS?
14.2 mm General Purpose Blue 7-Segment Display: CA, RH DP, Gray Surface; MinimumIntensity: 2020 ucd; Note: IF = 10 mA
footprint H (LED, 7-Segment Display, 14.2 mm, RHD; 10 Leads; Row Space 15.24 mm; Pitch 2.54 mm)
simulation model HDSP_501B (SUBCKT)
pins: 1 e "Cathode", 2 d "Cathode", 3 A "Common Anode", 4 c "Cathode", 5 DP "Cathode", 6 b "Cathode", 7 a "Cathode", 8 A "Common Anode", 9 f "Cathode", 10 g "Cathode"

## Dpy Blue-CC
designator DS?
14.2 mm General Purpose Blue 7-Segment Display: CC, RH DP, Gray Surface; MinimumIntensity: 2020 ucd; Note: IF = 10 mA
footprint H (LED, 7-Segment Display, 14.2 mm, RHD; 10 Leads; Row Space 15.24 mm; Pitch 2.54 mm)
simulation model HDSP_503B (SUBCKT)
pins: 1 e "Anode", 2 d "Anode", 3 K "Common Cathode", 4 c "Anode", 5 DP "Anode", 6 b "Anode", 7 a "Anode", 8 K "Common Cathode", 9 f "Anode", 10 g "Anode"

## Dpy Green-CA
designator DS?
7.62 mm Black Surface Green 7-Segment Display: CA, RH DP; MinimumIntensity: 860 ucd; Note: IF = 10 mA; Note: Pins 1 and 6 are redundant Anodes.
footprint A (LED, 7-Segment Display, 7.62 mm, RHD; 10 Leads; Row Space 5.08 mm; Pitch 2.54 mm)
simulation model HDSP_A511 (SUBCKT)
pins: 1 A "Anode", 2 f "Cathode", 3 g "Cathode", 4 e "Cathode", 5 d "Cathode", 6 A "Anode", 7 DP "Cathode", 8 c "Cathode", 9 b "Cathode", 10 a "Cathode"

## Dpy Green-CC
designator DS?
7.62 mm Black Surface Green 7-Segment Display: CC, RH DP; MinimumIntensity: 860 ucd; Note: IF = 10 mA; Note: Pins 1 and 6 are redundant Cathodes.
footprint A (LED, 7-Segment Display, 7.62 mm, RHD; 10 Leads; Row Space 5.08 mm; Pitch 2.54 mm)
simulation model HDSP_A513 (SUBCKT)
pins: 1 K "Cathode", 2 f "Anode", 3 g "Anode", 4 e "Anode", 5 d "Anode", 6 K "Cathode", 7 DP "Anode", 8 c "Anode", 9 b "Anode", 10 a "Anode"

## Dpy Overflow
designator DS?
7.62 mm HER 7-Segment Display: Universal ±1 Overflow, RH DP; MinimumIntensity: 340 ucd; Note: IF = 5 mA; Colour: High Efficiency Red (HER); Note: No pins are present in positions 2 and 9.
footprint A-12 (LED, Universal ±1 Overflow, 7.62 mm, RHD; 14 Leads (2 Absent); Row Space 7.62 mm; Pitch 2.54 mm)
simulation model 5082_7616 (SUBCKT)
pins: 1 d "Anode", 3 d "Cathode", 4 c "Cathode", 5 e "Cathode", 6 e "Anode", 7 c "Anode", 8 DP "Anode", 10 DP "Cathode", 11 b "Cathode", 12 a "Cathode", 13 a "Anode", 14 b "Anode"

## Dpy Red-CA
designator DS?
7.62 mm Black Surface HER 7-Segment Display: CA, RH DP; MinimumIntensity: 360 ucd; Note: IF = 5 mA; Colour: High Efficiency Red (HER); Note: Pins 1 and 6 are redundant Anodes.
footprint A (LED, 7-Segment Display, 7.62 mm, RHD; 10 Leads; Row Space 5.08 mm; Pitch 2.54 mm)
simulation model HDSP_A211 (SUBCKT)
pins: 1 A "Anode", 2 f "Cathode", 3 g "Cathode", 4 e "Cathode", 5 d "Cathode", 6 A "Anode", 7 DP "Cathode", 8 c "Cathode", 9 b "Cathode", 10 a "Cathode"

## Dpy Red-CC
designator DS?
7.62 mm Black Surface HER 7-Segment Display: CC, RH DP; MinimumIntensity: 360 ucd; Note: IF = 5 mA; Colour: High Efficiency Red (HER); Note: Pins 1 and 6 are redundant Cathodes.
footprint A (LED, 7-Segment Display, 7.62 mm, RHD; 10 Leads; Row Space 5.08 mm; Pitch 2.54 mm)
simulation model HDSP_A213 (SUBCKT)
pins: 1 K "Cathode", 2 f "Anode", 3 g "Anode", 4 e "Anode", 5 d "Anode", 6 K "Cathode", 7 DP "Anode", 8 c "Anode", 9 b "Anode", 10 a "Anode"

## Dpy Yellow-CA
designator DS?
7.6 mm Micro Bright Yellow 7-Segment Display: CA, RH DP; MinimumIntensity: 225 ucd; Note: IF = 5 mA; Note: Pins 1 and 6 are redundant Anodes.
footprint A (LED, 7-Segment Display, 7.62 mm, RHD; 10 Leads; Row Space 5.08 mm; Pitch 2.54 mm)
simulation model HDSP_7401 (SUBCKT)
pins: 1 A "Anode", 2 f "Cathode", 3 g "Cathode", 4 e "Cathode", 5 d "Cathode", 6 A "Anode", 7 DP "Cathode", 8 c "Cathode", 9 b "Cathode", 10 a "Cathode"

## Dpy Yellow-CC
designator DS?
7.6 mm Micro Bright Yellow 7-Segment Display: CC, RH DP; MinimumIntensity: 225 ucd; Note: IF = 5 mA; Note: Pins 1 and 6 are redundant Cathodes.
footprint A (LED, 7-Segment Display, 7.62 mm, RHD; 10 Leads; Row Space 5.08 mm; Pitch 2.54 mm)
simulation model HDSP_7403 (SUBCKT)
pins: 1 K "Cathode", 2 f "Anode", 3 g "Anode", 4 e "Anode", 5 d "Anode", 6 K "Cathode", 7 DP "Anode", 8 c "Anode", 9 b "Anode", 10 a "Anode"

## Edge Con 22
designator J?
22-Pin Edge Connector
footprint PIN22 (Connector; Edge; 22 Position)
signal-integrity model Connector
pins: 1, 2, 3, 4, 5, 6, 7, 8, 9, 10, 11, 12, 13, 14, 15, 16, 17, 18, 19, 20, 21, 22

## Edge Con 44
designator J?
44-Pin Edge Connector
footprint PIN44 (Connector; Edge; 44 Position)
signal-integrity model Connector
pins: 1, 2, 3, 4, 5, 6, 7, 8, 9, 10, 11, 12, 13, 14, 15, 16, 17, 18, 19, 20, 21, 22, 23 A, 24 B, 25 C, 26 D, 27 E, 28 F, 29 G, 30 H, 31 J, 32 K, 33 L, 34 M, 35 N, 36 P, 37 R, 38 S, 39 T, 40 U, 41 V, 42 W, 43 X, 44 Z

## Edge Con 50
designator J?
50-Pin Edge Connector
footprint PIN50 (Connector; Edge; 50 Position)
signal-integrity model Connector
pins: 1, 2, 3, 4, 5, 6, 7, 8, 9, 10, 11, 12, 13, 14, 15, 16, 17, 18, 19, 20, 21, 22, 23, 24, 25, 26, 27, 28, 29, 30, 31, 32, 33, 34, 35, 36, 37, 38, 39, 40, 41, 42, 43, 44, 45, 46, 47, 48, 49, 50

## Fuse 1
designator F?
Fuse
footprint PIN-W2/E2.8 (Thru-Hole; 2 Leads)
simulation model FUSE (Spice Subcircuit)
pins: 1, 2

## Fuse 2
designator F?
Fuse
footprint PIN-W2/E2.8 (Thru-Hole; 2 Leads)
simulation model FUSE (Spice Subcircuit)
pins: 1, 2

## Fuse Thermal
designator F?
Thermal Fuse
footprint PIN-W2/E2.8 (Thru-Hole; 2 Leads)
pins: 1, 2

## Header 2
designator P?
Header, 2-Pin
footprint HDR1X2 (Connector; Header; 2 Position)
signal-integrity model Connector
pins: 1, 2

## Header 2H
designator P?
Header, 2-Pin, Right Angle
footprint HDR1X2H (Connector; Header; 2 Position; Right Angle)
signal-integrity model Connector
pins: 1, 2

## Header 2X2
designator P?
Header, 2-Pin, Dual row
footprint HDR2X2 (Connector; Header; 2x2 Position)
signal-integrity model Connector
pins: 1, 2, 3, 4

## Header 2X2H
designator P?
Header, 2-Pin, Dual row, Right Angle
footprint HDR2X2H (Connector; Header; 2x2 Position; Right Angle)
signal-integrity model Connector
pins: 1, 2, 3, 4

## Header 3
designator P?
Header, 3-Pin
footprint HDR1X3 (Connector; Header; 3 Position)
signal-integrity model Connector
pins: 1, 2, 3

## Header 3H
designator P?
Header, 3-Pin, Right Angle
footprint HDR1X3H (Connector; Header; 3 Position; Right Angle)
signal-integrity model Connector
pins: 1, 2, 3

## Header 3X2
designator P?
Header, 3-Pin, Dual row
footprint HDR2X3 (Connector; Header; 3x2 Position)
signal-integrity model Connector
pins: 1, 2, 3, 4, 5, 6

## Header 3X2A
designator P?
Header, 3-Pin, Dual row
footprint HDR2X3_CEN (Connector; Header; 3x2 Position)
signal-integrity model Connector
pins: 1, 2, 3, 4, 5, 6

## Header 3X2H
designator P?
Header, 3-Pin, Dual row, Right Angle
footprint HDR2X3H (Connector; Header; 3x2 Position; Right Angle)
signal-integrity model Connector
pins: 1, 2, 3, 4, 5, 6

## Header 4
designator P?
Header, 4-Pin
footprint HDR1X4 (Connector; Header; 4 Position)
signal-integrity model Connector
pins: 1, 2, 3, 4

## Header 4H
designator P?
Header, 4-Pin, Right Angle
footprint HDR1X4H (Connector; Header; 4 Position; Right Angle)
signal-integrity model Connector
pins: 1, 2, 3, 4

## Header 4X2
designator P?
Header, 4-Pin, Dual row
footprint HDR2X4 (Connector; Header; 4x2 Position)
signal-integrity model Connector
pins: 1, 2, 3, 4, 5, 6, 7, 8

## Header 4X2A
designator P?
Header, 4-Pin, Dual row
footprint HDR2X4_CEN (Connector; Header; 4x2 Position)
signal-integrity model Connector
pins: 1, 2, 3, 4, 5, 6, 7, 8

## Header 4X2H
designator P?
Header, 4-Pin, Dual row, Right Angle
footprint HDR2X4H (Connector; Header; 4x2 Position; Right Angle)
signal-integrity model Connector
pins: 1, 2, 3, 4, 5, 6, 7, 8

## Header 5
designator P?
Header, 5-Pin
footprint HDR1X5 (Connector; Header; 5 Position)
signal-integrity model Connector
pins: 1, 2, 3, 4, 5

## Header 5H
designator P?
Header, 5-Pin, Right Angle
footprint HDR1X5H (Connector; Header; 5 Position; Right Angle)
signal-integrity model Connector
pins: 1, 2, 3, 4, 5

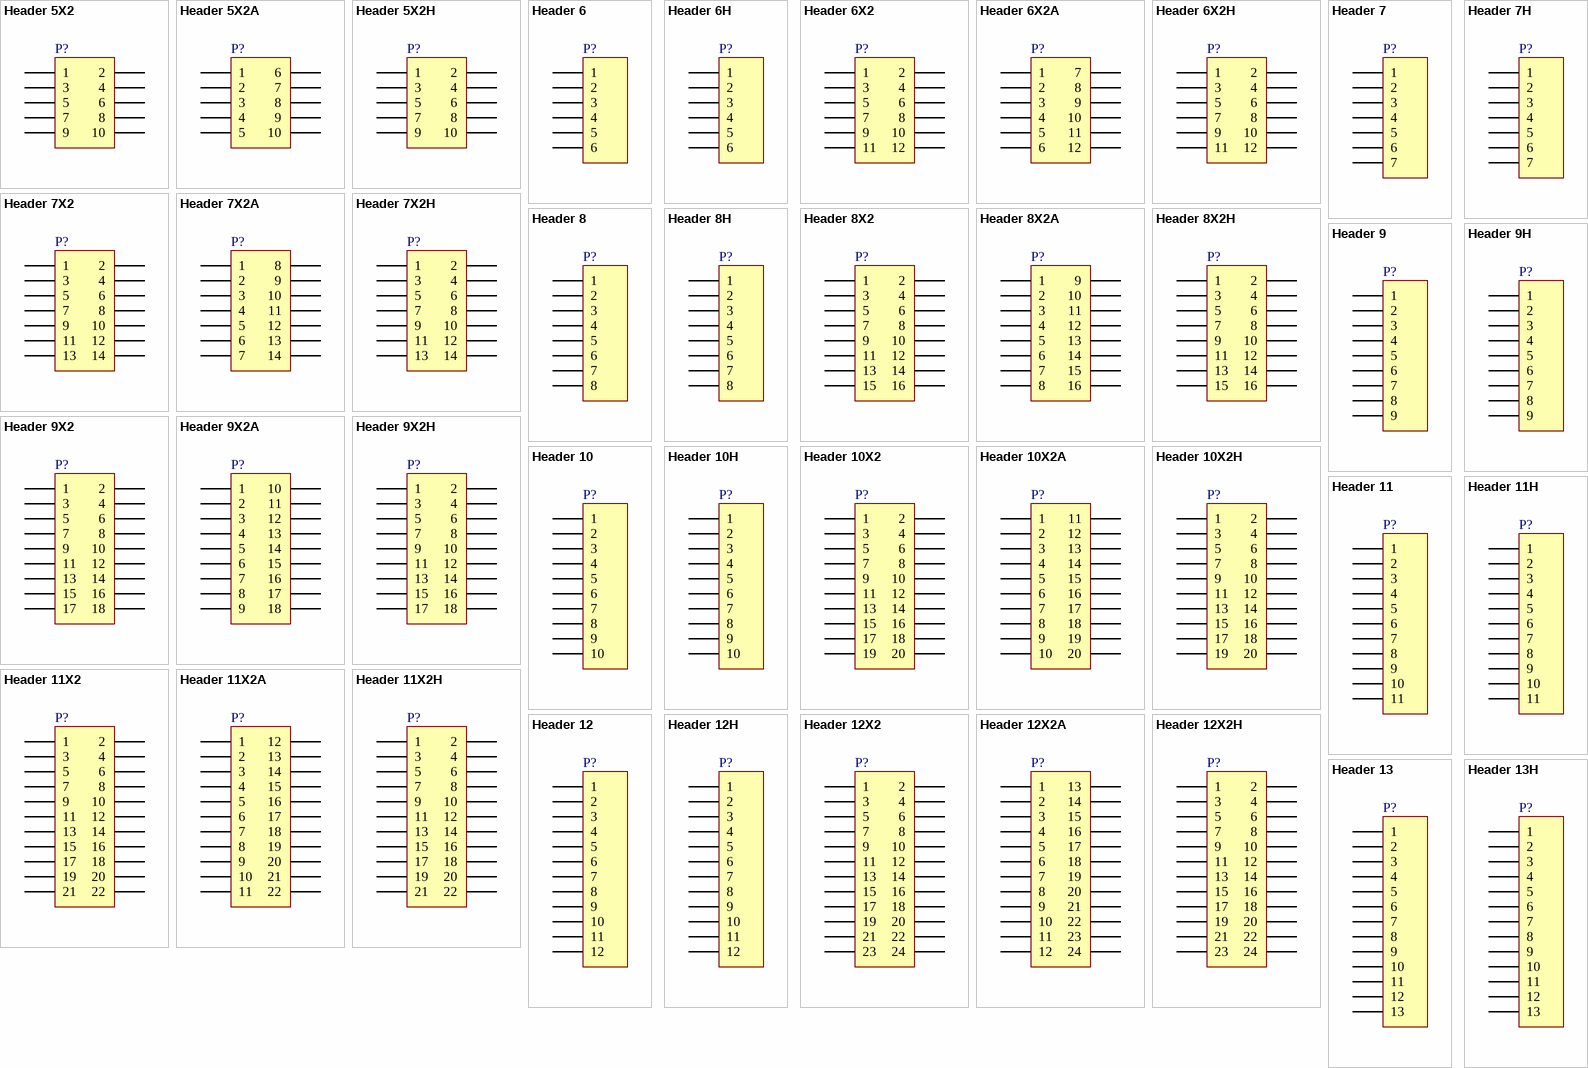
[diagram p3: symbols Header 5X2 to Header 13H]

## Header 5X2
designator P?
Header, 5-Pin, Dual row
footprint HDR2X5 (Connector; Header; 5x2 Position)
signal-integrity model Connector
pins: 1, 2, 3, 4, 5, 6, 7, 8, 9, 10

## Header 5X2A
designator P?
Header, 5-Pin, Dual row
footprint HDR2X5_CEN (Connector; Header; 5x2 Position)
signal-integrity model Connector
pins: 1, 2, 3, 4, 5, 6, 7, 8, 9, 10

## Header 5X2H
designator P?
Header, 5-Pin, Dual row, Right Angle
footprint HDR2X5H (Connector; Header; 5x2 Position; Right Angle)
signal-integrity model Connector
pins: 1, 2, 3, 4, 5, 6, 7, 8, 9, 10

## Header 6
designator P?
Header, 6-Pin
footprint HDR1X6 (Connector; Header; 6 Position)
signal-integrity model Connector
pins: 1, 2, 3, 4, 5, 6

## Header 6H
designator P?
Header, 6-Pin, Right Angle
footprint HDR1X6H (Connector; Header; 6 Position; Right Angle)
signal-integrity model Connector
pins: 1, 2, 3, 4, 5, 6

## Header 6X2
designator P?
Header, 6-Pin, Dual row
footprint HDR2X6 (Connector; Header; 6x2 Position)
signal-integrity model Connector
pins: 1, 2, 3, 4, 5, 6, 7, 8, 9, 10, 11, 12

## Header 6X2A
designator P?
Header, 6-Pin, Dual row
footprint HDR2X6_CEN (Connector; Header; 6x2 Position)
signal-integrity model Connector
pins: 1, 2, 3, 4, 5, 6, 7, 8, 9, 10, 11, 12

## Header 6X2H
designator P?
Header, 6-Pin, Dual row, Right Angle
footprint HDR2X6H (Connector; Header; 6x2 Position; Right Angle)
signal-integrity model Connector
pins: 1, 2, 3, 4, 5, 6, 7, 8, 9, 10, 11, 12

## Header 7
designator P?
Header, 7-Pin
footprint HDR1X7 (Connector; Header; 7 Position)
signal-integrity model Connector
pins: 1, 2, 3, 4, 5, 6, 7

## Header 7H
designator P?
Header, 7-Pin, Right Angle
footprint HDR1X7H (Connector; Header; 7 Position; Right Angle)
signal-integrity model Connector
pins: 1, 2, 3, 4, 5, 6, 7

## Header 7X2
designator P?
Header, 7-Pin, Dual row
footprint HDR2X7 (Connector; Header; 7x2 Position)
signal-integrity model Connector
pins: 1, 2, 3, 4, 5, 6, 7, 8, 9, 10, 11, 12, 13, 14

## Header 7X2A
designator P?
Header, 7-Pin, Dual row
footprint HDR2X7_CEN (Connector; Header; 7x2 Position)
signal-integrity model Connector
pins: 1, 2, 3, 4, 5, 6, 7, 8, 9, 10, 11, 12, 13, 14

## Header 7X2H
designator P?
Header, 7-Pin, Dual row, Right Angle
footprint HDR2X7H (Connector; Header; 7x2 Position; Right Angle)
signal-integrity model Connector
pins: 1, 2, 3, 4, 5, 6, 7, 8, 9, 10, 11, 12, 13, 14

## Header 8
designator P?
Header, 8-Pin
footprint HDR1X8 (Connector; Header; 8 Position)
signal-integrity model Connector
pins: 1, 2, 3, 4, 5, 6, 7, 8

## Header 8H
designator P?
Header, 8-Pin, Right Angle
footprint HDR1X8H (Connector; Header; 8 Position; Right Angle)
signal-integrity model Connector
pins: 1, 2, 3, 4, 5, 6, 7, 8

## Header 8X2
designator P?
Header, 8-Pin, Dual row
footprint HDR2X8 (Connector; Header; 8x2 Position)
signal-integrity model Connector
pins: 1, 2, 3, 4, 5, 6, 7, 8, 9, 10, 11, 12, 13, 14, 15, 16

## Header 8X2A
designator P?
Header, 8-Pin, Dual row
footprint HDR2X8_CEN (Connector; Header; 8x2 Position)
signal-integrity model Connector
pins: 1, 2, 3, 4, 5, 6, 7, 8, 9, 10, 11, 12, 13, 14, 15, 16

## Header 8X2H
designator P?
Header, 8-Pin, Dual row, Right Angle
footprint HDR2X8H (Connector; Header; 8x2 Position; Right Angle)
signal-integrity model Connector
pins: 1, 2, 3, 4, 5, 6, 7, 8, 9, 10, 11, 12, 13, 14, 15, 16

## Header 9
designator P?
Header, 9-Pin
footprint HDR1X9 (Connector; Header; 9 Position)
signal-integrity model Connector
pins: 1, 2, 3, 4, 5, 6, 7, 8, 9

## Header 9H
designator P?
Header, 9-Pin, Right Angle
footprint HDR1X9H (Connector; Header; 9 Position; Right Angle)
signal-integrity model Connector
pins: 1, 2, 3, 4, 5, 6, 7, 8, 9

## Header 9X2
designator P?
Header, 9-Pin, Dual row
footprint HDR2X9 (Connector; Header; 9x2 Position)
signal-integrity model Connector
pins: 1, 2, 3, 4, 5, 6, 7, 8, 9, 10, 11, 12, 13, 14, 15, 16, 17, 18

## Header 9X2A
designator P?
Header, 9-Pin, Dual row
footprint HDR2X9_CEN (Connector; Header; 9x2 Position)
signal-integrity model Connector
pins: 1, 2, 3, 4, 5, 6, 7, 8, 9, 10, 11, 12, 13, 14, 15, 16, 17, 18

## Header 9X2H
designator P?
Header, 9-Pin, Dual row, Right Angle
footprint HDR2X9H (Connector; Header; 9x2 Position; Right Angle)
signal-integrity model Connector
pins: 1, 2, 3, 4, 5, 6, 7, 8, 9, 10, 11, 12, 13, 14, 15, 16, 17, 18

## Header 10
designator P?
Header, 10-Pin
footprint HDR1X10 (Connector; Header; 10 Position)
signal-integrity model Connector
pins: 1, 2, 3, 4, 5, 6, 7, 8, 9, 10

## Header 10H
designator P?
Header, 10-Pin, Right Angle
footprint HDR1X10H (Connector; Header; 10 Position; Right Angle)
signal-integrity model Connector
pins: 1, 2, 3, 4, 5, 6, 7, 8, 9, 10

## Header 10X2
designator P?
Header, 10-Pin, Dual row
footprint HDR2X10 (Connector; Header; 10x2 Position)
signal-integrity model Connector
pins: 1, 2, 3, 4, 5, 6, 7, 8, 9, 10, 11, 12, 13, 14, 15, 16, 17, 18, 19, 20

## Header 10X2A
designator P?
Header, 10-Pin, Dual row
footprint HDR2X10_CEN (Connector; Header; 10x2 Position)
signal-integrity model Connector
pins: 1, 2, 3, 4, 5, 6, 7, 8, 9, 10, 11, 12, 13, 14, 15, 16, 17, 18, 19, 20

## Header 10X2H
designator P?
Header, 10-Pin, Dual row, Right Angle
footprint HDR2X10H (Connector; Header; 10x2 Position; Right Angle)
signal-integrity model Connector
pins: 1, 2, 3, 4, 5, 6, 7, 8, 9, 10, 11, 12, 13, 14, 15, 16, 17, 18, 19, 20

## Header 11
designator P?
Header, 11-Pin
footprint HDR1X11 (Connector; Header; 11 Position)
signal-integrity model Connector
pins: 1, 2, 3, 4, 5, 6, 7, 8, 9, 10, 11

## Header 11H
designator P?
Header, 11-Pin, Right Angle
footprint HDR1X11H (Connector; Header; 11 Position; Right Angle)
signal-integrity model Connector
pins: 1, 2, 3, 4, 5, 6, 7, 8, 9, 10, 11

## Header 11X2
designator P?
Header, 11-Pin, Dual row
footprint HDR2X11 (Connector; Header; 11x2 Position)
signal-integrity model Connector
pins: 1, 2, 3, 4, 5, 6, 7, 8, 9, 10, 11, 12, 13, 14, 15, 16, 17, 18, 19, 20, 21, 22

## Header 11X2A
designator P?
Header, 11-Pin, Dual row
footprint HDR2X11_CEN (Connector; Header; 11x2 Position)
signal-integrity model Connector
pins: 1, 2, 3, 4, 5, 6, 7, 8, 9, 10, 11, 12, 13, 14, 15, 16, 17, 18, 19, 20, 21, 22

## Header 11X2H
designator P?
Header, 11-Pin, Dual row, Right Angle
footprint HDR2X11H (Connector; Header; 11x2 Position; Right Angle)
signal-integrity model Connector
pins: 1, 2, 3, 4, 5, 6, 7, 8, 9, 10, 11, 12, 13, 14, 15, 16, 17, 18, 19, 20, 21, 22

## Header 12
designator P?
Header, 12-Pin
footprint HDR1X12 (Connector; Header; 12 Position)
signal-integrity model Connector
pins: 1, 2, 3, 4, 5, 6, 7, 8, 9, 10, 11, 12

## Header 12H
designator P?
Header, 12-Pin, Right Angle
footprint HDR1X12H (Connector; Header; 12 Position; Right Angle)
signal-integrity model Connector
pins: 1, 2, 3, 4, 5, 6, 7, 8, 9, 10, 11, 12

## Header 12X2
designator P?
Header, 12-Pin, Dual row
footprint HDR2X12 (Connector; Header; 12x2 Position)
signal-integrity model Connector
pins: 1, 2, 3, 4, 5, 6, 7, 8, 9, 10, 11, 12, 13, 14, 15, 16, 17, 18, 19, 20, 21, 22, 23, 24

## Header 12X2A
designator P?
Header, 12-Pin, Dual row
footprint HDR2X12_CEN (Connector; Header; 12x2 Position)
signal-integrity model Connector
pins: 1, 2, 3, 4, 5, 6, 7, 8, 9, 10, 11, 12, 13, 14, 15, 16, 17, 18, 19, 20, 21, 22, 23, 24

## Header 12X2H
designator P?
Header, 12-Pin, Dual row, Right Angle
footprint HDR2X12H (Connector; Header; 12x2 Position; Right Angle)
signal-integrity model Connector
pins: 1, 2, 3, 4, 5, 6, 7, 8, 9, 10, 11, 12, 13, 14, 15, 16, 17, 18, 19, 20, 21, 22, 23, 24

## Header 13
designator P?
Header, 13-Pin
footprint HDR1X13 (Connector; Header; 13 Position)
signal-integrity model Connector
pins: 1, 2, 3, 4, 5, 6, 7, 8, 9, 10, 11, 12, 13

## Header 13H
designator P?
Header, 13-Pin, Right Angle
footprint HDR1X13H (Connector; Header; 13 Position; Right Angle)
signal-integrity model Connector
pins: 1, 2, 3, 4, 5, 6, 7, 8, 9, 10, 11, 12, 13

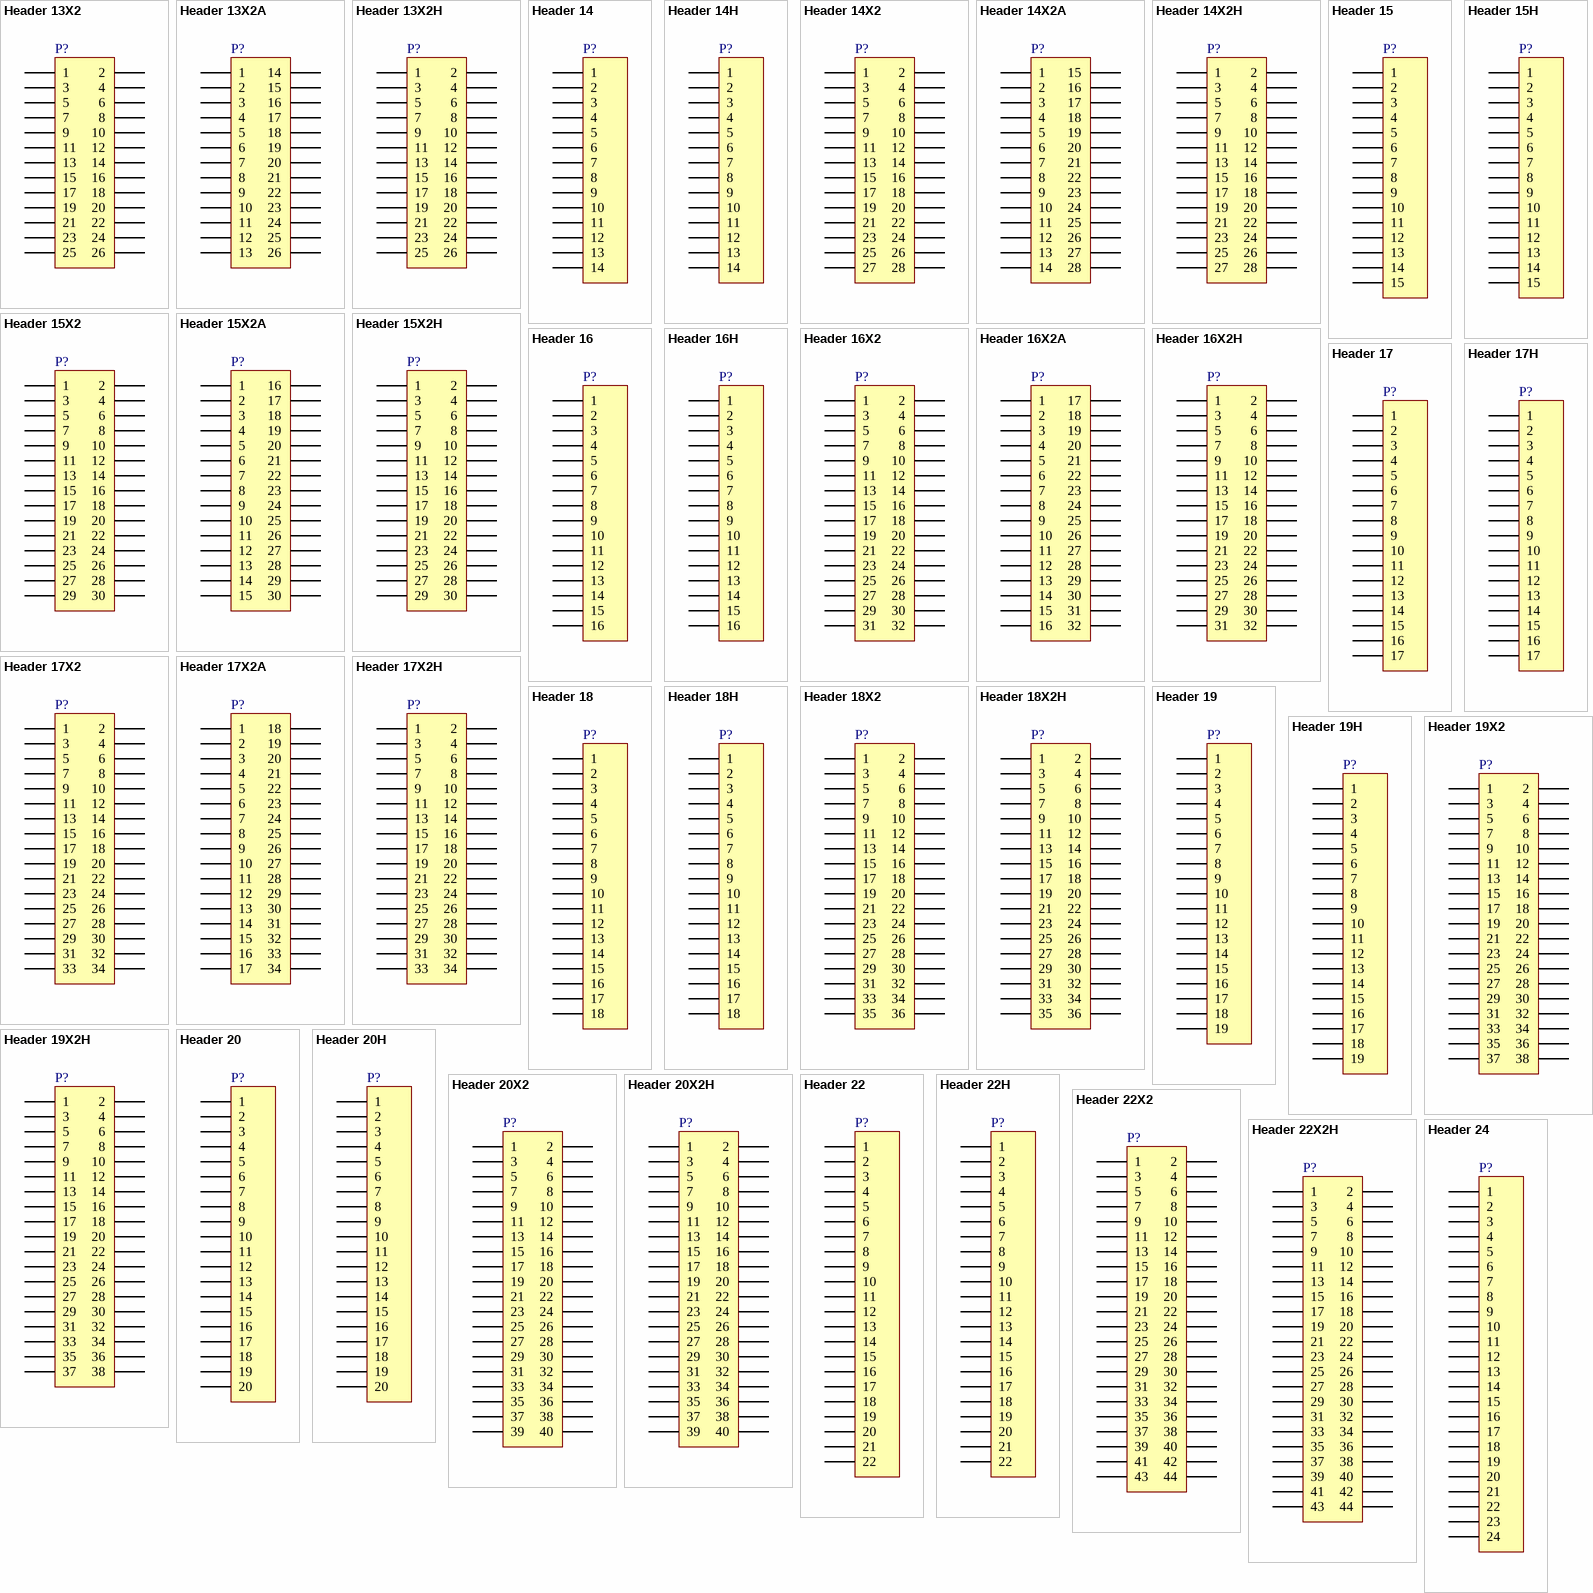
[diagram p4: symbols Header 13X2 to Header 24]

## Header 13X2
designator P?
Header, 13-Pin, Dual row
footprint HDR2X13 (Connector; Header; 13x2 Position)
signal-integrity model Connector
pins: 1, 2, 3, 4, 5, 6, 7, 8, 9, 10, 11, 12, 13, 14, 15, 16, 17, 18, 19, 20, 21, 22, 23, 24, 25, 26

## Header 13X2A
designator P?
Header, 13-Pin, Dual row
footprint HDR2X13_CEN (Connector; Header; 13x2 Position)
signal-integrity model Connector
pins: 1, 2, 3, 4, 5, 6, 7, 8, 9, 10, 11, 12, 13, 14, 15, 16, 17, 18, 19, 20, 21, 22, 23, 24, 25, 26

## Header 13X2H
designator P?
Header, 13-Pin, Dual row, Right Angle
footprint HDR2X13H (Connector; Header; 13x2 Position; Right Angle)
signal-integrity model Connector
pins: 1, 2, 3, 4, 5, 6, 7, 8, 9, 10, 11, 12, 13, 14, 15, 16, 17, 18, 19, 20, 21, 22, 23, 24, 25, 26

## Header 14
designator P?
Header, 14-Pin
footprint HDR1X14 (Connector; Header; 14 Position)
signal-integrity model Connector
pins: 1, 2, 3, 4, 5, 6, 7, 8, 9, 10, 11, 12, 13, 14

## Header 14H
designator P?
Header, 14-Pin, Right Angle
footprint HDR1X14H (Connector; Header; 14 Position; Right Angle)
signal-integrity model Connector
pins: 1, 2, 3, 4, 5, 6, 7, 8, 9, 10, 11, 12, 13, 14

## Header 14X2
designator P?
Header, 14-Pin, Dual row
footprint HDR2X14 (Connector; Header; 14x2 Position)
signal-integrity model Connector
pins: 1, 2, 3, 4, 5, 6, 7, 8, 9, 10, 11, 12, 13, 14, 15, 16, 17, 18, 19, 20, 21, 22, 23, 24, 25, 26, 27, 28

## Header 14X2A
designator P?
Header, 14-Pin, Dual row
footprint HDR2X14_CEN (Connector; Header; 14x2 Position)
signal-integrity model Connector
pins: 1, 2, 3, 4, 5, 6, 7, 8, 9, 10, 11, 12, 13, 14, 15, 16, 17, 18, 19, 20, 21, 22, 23, 24, 25, 26, 27, 28

## Header 14X2H
designator P?
Header, 14-Pin, Dual row, Right Angle
footprint HDR2X14H (Connector; Header; 14x2 Position; Right Angle)
signal-integrity model Connector
pins: 1, 2, 3, 4, 5, 6, 7, 8, 9, 10, 11, 12, 13, 14, 15, 16, 17, 18, 19, 20, 21, 22, 23, 24, 25, 26, 27, 28

## Header 15
designator P?
Header, 15-Pin
footprint HDR1X15 (Connector; Header; 15 Position)
signal-integrity model Connector
pins: 1, 2, 3, 4, 5, 6, 7, 8, 9, 10, 11, 12, 13, 14, 15

## Header 15H
designator P?
Header, 15-Pin, Right Angle
footprint HDR1X15H (Connector; Header; 15 Position; Right Angle)
signal-integrity model Connector
pins: 1, 2, 3, 4, 5, 6, 7, 8, 9, 10, 11, 12, 13, 14, 15

## Header 15X2
designator P?
Header, 15-Pin, Dual row
footprint HDR2X15 (Connector; Header; 15x2 Position)
signal-integrity model Connector
pins: 1, 2, 3, 4, 5, 6, 7, 8, 9, 10, 11, 12, 13, 14, 15, 16, 17, 18, 19, 20, 21, 22, 23, 24, 25, 26, 27, 28, 29, 30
